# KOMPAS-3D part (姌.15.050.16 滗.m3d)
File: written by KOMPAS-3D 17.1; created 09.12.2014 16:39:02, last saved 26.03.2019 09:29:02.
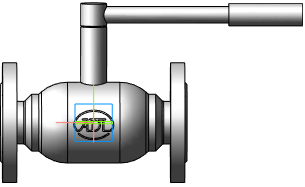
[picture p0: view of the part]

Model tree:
1. Операция без истории:4  (labels: Сталь 20  ГОСТ 1050-88)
